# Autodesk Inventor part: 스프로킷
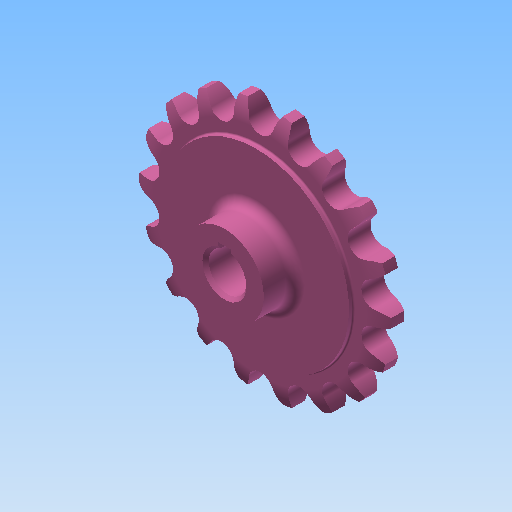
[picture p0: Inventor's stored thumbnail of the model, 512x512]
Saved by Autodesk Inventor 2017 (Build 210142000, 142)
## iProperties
Created: 2016-03
Part Number: 스프로킷
Material: 강철, 탄소
Document SubType Name: Modeling
Designer: mduedu
Density: 7.87 g/cm^3
Mass: 301.818 g
Surface Area: 124.882 cm^2
Volume: 38.3505 cm^3
Appearance: 분홍색
Author: mduedu
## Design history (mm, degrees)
sketch "스케치1"
  geometry: L1 (0, 5)-(29.5, 5); L2 (29.5, 5)-(29.5, 4.1); L3 (30, 3.6)-(33.625, 3.6); L4 (40, 2)-(40, 0); L5 (40, 0)-(0, 0); L6 (0, 0)-(0, 5); L7 (0, -5)-(29.5, -5); L8 (29.5, -5)-(29.5, -4.1); L9 (30, -3.6)-(33.625, -3.6); L10 (40, -2)-(40, 0); L11 (0, 0)-(0, -5); A1 r 13.5 centre (33.625, -9.9) between (40, 2) and (33.625, 3.6); A2 r 13.5 centre (33.625, 9.9) between (33.625, -3.6) and (40, -2); A3 r 0.5 centre (30, 4.1) between (29.5, 4.1) and (30, 3.6); A4 r 0.5 centre (30, -4.1) between (30, -3.6) and (29.5, -4.1); 2 further points
  constraints: 22 end point, 8 point on circle, 6 symmetric about line, 5 tangent, 4 centre point, 4 parallel, 4 point on line, 1 equal radius, 1 horizontal, 1 perpendicular, 1 other
  dimensions: "d0" = 80 diameter of L4 L6; "d2" = 59 diameter of L2 L6; "d3" = 1.6 vertical distance of L4.start L3.end; "d4" = 3.6 distance from line of L4.end L3; "d5" = 5 distance between parallel lines of L5 L1; "d6" = 13.5 radius of A1; "d15" = 0.5 radius of A3
revolve "회전1" sketch "스케치1" stored, may be unused: angle "d7" = 90 deg
sketch "스케치2" dims "d8" = 65.2, "d11" = 80
  geometry: L1 (0, 0)-(0, 32.6); A1 r 36.57 centre (0, 0) between (-16.231, 32.771) and (0, 36.57); A2 r 3.97 centre (0, 36.57) between (-3.866, 35.665) and (0, 32.6); A3 r 12.7 centre (-16.231, 32.771) between (-3.866, 35.665) and (-5.534, 39.615); A4 r 12.7 centre (16.231, 32.771) between (5.534, 39.615) and (3.866, 35.665); A5 r 3.97 centre (0, 36.57) between (0, 32.6) and (3.866, 35.665); A6 r 40 centre (0, 0) between (5.534, 39.615) and (-5.534, 39.615); 2 further points
  constraints: 12 point on circle, 6 centre point, 4 coincident, 3 symmetric about line, 2 end point, 1 point on line, 1 tangent, 1 vertical, 1 vertical alignment, 7 other
  dimensions: "d10" = 73.14 diameter of A1; "d12" = 12.7 radius of A3
extrude "돌출1" cut sketch "스케치2" stored distance "d13" = 10; taper "d14" = 0 deg
sketch "스케치3"
  geometry: C1 r 12.5 at (0, 0); 1 further point
  constraints: 1 centre point, 1 coincident
  dimensions: "d19" = 25 diameter of C1
extrude "돌출2" join sketch "스케치3" distance "d20" = 10; taper "d21" = 0 deg
fillet "모깎기1" dims "d22" = 3
sketch "스케치4"
  geometry: L1 (-2, 0)-(2, 0); L2 (2, 0)-(2, 7.8); L3 (2, 7.8)-(-2, 7.8); L4 (-2, 7.8)-(-2, 0); C1 r 6 at (0, 0); 2 further points
  constraints: 8 end point, 2 coincident, 2 parallel, 1 centre point, 1 horizontal, 1 midpoint, 1 perpendicular
  dimensions: "d23" = 12 diameter of C1; "d25" = 4 distance of L2.end L3.end; "d26" = 7.8 distance of L1.end L2.end
extrude "돌출3" cut sketch "스케치4" stored distance "d27" = 8; taper "d28" = 0 deg
chamfer "모따기2" distance "d42" = 1; stored, may be unused: second distance "d43" = 2, angle "d44" = 45 deg
node "솔리드1"
pattern_circular "원형 패턴1" dims angle "d17" = 360 deg
